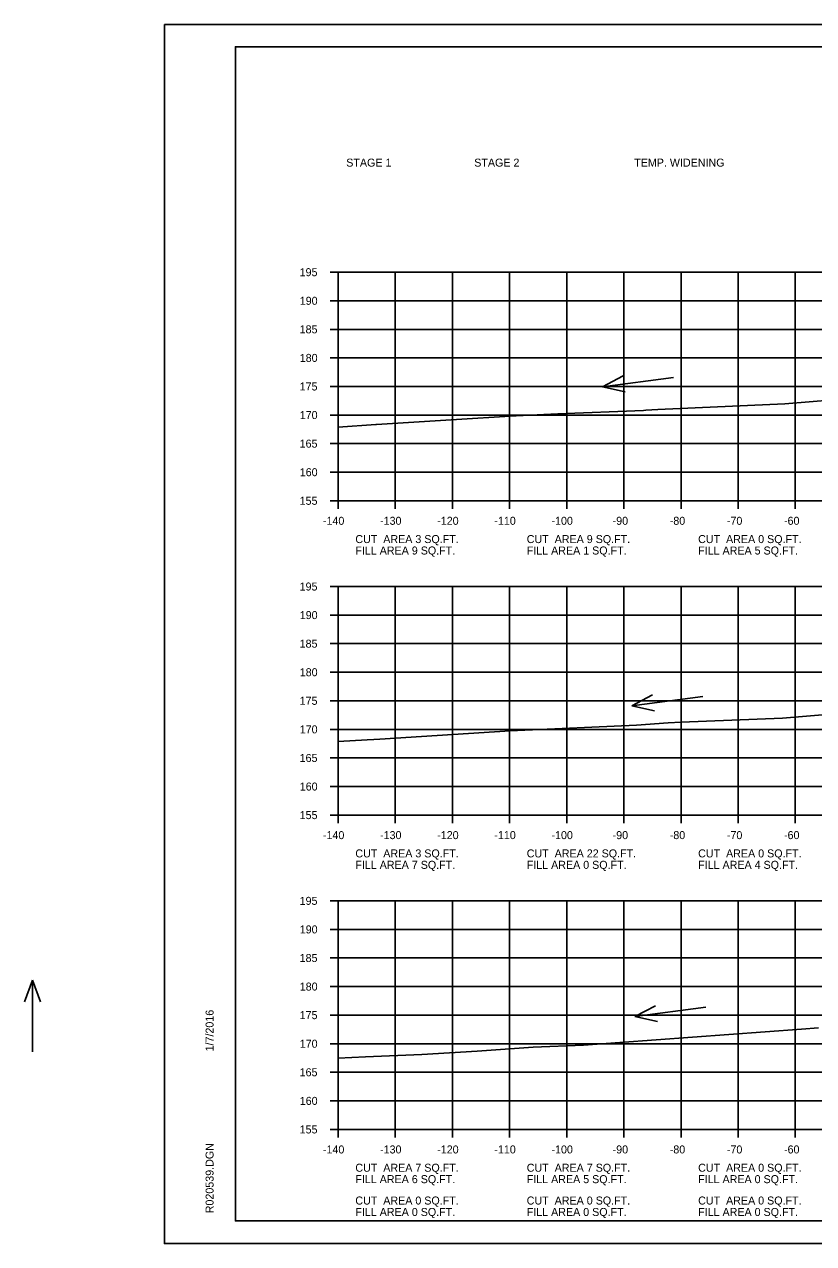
# Model space of a CAD drawing. Extents: x 915787 to 919910, y 133456 to 136717.
# Drawn here: x 916219.1 to 916357.2, y 133456 to 133669.4 of the extents above; entities that cross this region are included whole.
import ezdxf

# ---------------------------------------------------------------- set-up
doc = ezdxf.new("R2010")
doc.units = 0
for name, color, linetype in [('R_Axis', 7, 'Continuous'), ('R_Axis Annot', 7, 'Continuous'), ('R_Border', 7, 'Continuous'), ('R_Border Notes', 7, 'Continuous'), ('R_Exist Surface', 7, 'Continuous'), ('R_Grid', 7, 'Continuous'), ('R_No Plot', 7, 'Continuous'), ('R_Water Annot', 7, 'Continuous')]:
    doc.layers.add(name, color=color, linetype=linetype)

msp = doc.modelspace()

# ---------------------------------------------------------------- linework, layer by layer
at = {"layer": 'R_Axis'}
for p, q in [((916272.58, 133626.01), (916273.98, 133626.01)), ((916273.98, 133586.01), (916273.98, 133626.01)), ((916272.58, 133621.01), (916273.98, 133621.01)), ((916272.58, 133616.01), (916273.98, 133616.01)), ((916272.58, 133611.01), (916273.98, 133611.01)), ((916272.58, 133606.01), (916273.98, 133606.01)), ((916272.58, 133601.01), (916273.98, 133601.01)), ((916272.58, 133596.01), (916273.98, 133596.01)), ((916272.58, 133591.01), (916273.98, 133591.01)), ((916272.58, 133586.01), (916273.98, 133586.01)), ((916273.98, 133586.01), (916553.98, 133586.01)), ((916273.98, 133584.61), (916273.98, 133586.01)), ((916283.98, 133584.61), (916283.98, 133586.01)), ((916293.98, 133584.61), (916293.98, 133586.01)), ((916303.98, 133584.61), (916303.98, 133586.01)), ((916313.98, 133584.61), (916313.98, 133586.01)), ((916323.98, 133584.61), (916323.98, 133586.01)), ((916333.98, 133584.61), (916333.98, 133586.01)), ((916343.98, 133584.61), (916343.98, 133586.01)), ((916353.98, 133584.61), (916353.98, 133586.01)), ((916272.58, 133571.01), (916273.98, 133571.01)), ((916273.98, 133531.01), (916273.98, 133571.01)), ((916272.58, 133566.01), (916273.98, 133566.01)), ((916272.58, 133561.01), (916273.98, 133561.01)), ((916272.58, 133556.01), (916273.98, 133556.01)), ((916272.58, 133551.01), (916273.98, 133551.01)), ((916272.58, 133546.01), (916273.98, 133546.01)), ((916272.58, 133541.01), (916273.98, 133541.01)), ((916272.58, 133536.01), (916273.98, 133536.01)), ((916272.58, 133531.01), (916273.98, 133531.01)), ((916273.98, 133531.01), (916553.98, 133531.01)), ((916273.98, 133529.61), (916273.98, 133531.01)), ((916283.98, 133529.61), (916283.98, 133531.01)), ((916293.98, 133529.61), (916293.98, 133531.01)), ((916303.98, 133529.61), (916303.98, 133531.01)), ((916313.98, 133529.61), (916313.98, 133531.01)), ((916323.98, 133529.61), (916323.98, 133531.01)), ((916333.98, 133529.61), (916333.98, 133531.01)), ((916343.98, 133529.61), (916343.98, 133531.01)), ((916353.98, 133529.61), (916353.98, 133531.01)), ((916272.58, 133516.01), (916273.98, 133516.01)), ((916273.98, 133476.01), (916273.98, 133516.01)), ((916272.58, 133511.01), (916273.98, 133511.01)), ((916272.58, 133506.01), (916273.98, 133506.01)), ((916272.58, 133501.01), (916273.98, 133501.01)), ((916272.58, 133496.01), (916273.98, 133496.01)), ((916272.58, 133491.01), (916273.98, 133491.01)), ((916272.58, 133486.01), (916273.98, 133486.01)), ((916272.58, 133481.01), (916273.98, 133481.01)), ((916272.58, 133476.01), (916273.98, 133476.01)), ((916273.98, 133476.01), (916553.98, 133476.01)), ((916273.98, 133474.61), (916273.98, 133476.01)), ((916283.98, 133474.61), (916283.98, 133476.01)), ((916293.98, 133474.61), (916293.98, 133476.01)), ((916303.98, 133474.61), (916303.98, 133476.01)), ((916313.98, 133474.61), (916313.98, 133476.01)), ((916323.98, 133474.61), (916323.98, 133476.01)), ((916333.98, 133474.61), (916333.98, 133476.01)), ((916343.98, 133474.61), (916343.98, 133476.01)), ((916353.98, 133474.61), (916353.98, 133476.01))]:
    msp.add_line(p, q, dxfattribs=at)
at = {"layer": 'R_Border'}
for p, q in [((916255.98, 133665.47), (916572.16, 133665.47)), ((916255.98, 133460.01), (916255.98, 133665.47)), ((916255.98, 133460.01), (916255.98, 133460.01)), ((916572.16, 133460.01), (916255.98, 133460.01))]:
    msp.add_line(p, q, dxfattribs=at)
at = {"layer": 'R_Exist Surface'}
for points in [[(916273.98, 133598.91), (916280.55, 133599.33), (916280.71, 133599.34), (916293.73, 133600.17), (916305.04, 133600.88), (916305.14, 133600.89), (916312.44, 133601.2), (916327.43, 133601.83), (916327.8, 133601.84), (916329.93, 133601.97), (916352.13, 133602.95), (916364.93, 133604)], [(916273.98, 133543.89), (916279.05, 133544.21), (916280.2, 133544.26), (916281.28, 133544.3), (916304.08, 133545.74), (916305.35, 133545.83), (916326.18, 133546.72), (916331.72, 133547.13), (916334.02, 133547.28), (916351.75, 133547.99), (916354.57, 133548.22), (916365.66, 133549.14)], [(916273.98, 133488.49), (916278.75, 133488.69), (916288.59, 133489.1), (916298.32, 133489.7), (916308.11, 133490.4), (916316.93, 133490.77), (916355.08, 133493.56), (916358.02, 133493.77)]]:
    msp.add_lwpolyline(points, dxfattribs=at)
at = {"layer": 'R_Grid'}
for p, q in [((916273.98, 133626.01), (916553.98, 133626.01)), ((916273.98, 133586.01), (916273.98, 133626.01)), ((916283.98, 133586.01), (916283.98, 133626.01)), ((916293.98, 133586.01), (916293.98, 133626.01)), ((916303.98, 133586.01), (916303.98, 133626.01)), ((916313.98, 133586.01), (916313.98, 133626.01)), ((916323.98, 133586.01), (916323.98, 133626.01)), ((916333.98, 133586.01), (916333.98, 133626.01)), ((916343.98, 133586.01), (916343.98, 133626.01)), ((916353.98, 133586.01), (916353.98, 133626.01)), ((916273.98, 133621.01), (916553.98, 133621.01)), ((916273.98, 133616.01), (916553.98, 133616.01)), ((916273.98, 133611.01), (916553.98, 133611.01)), ((916273.98, 133606.01), (916553.98, 133606.01)), ((916273.98, 133601.01), (916553.98, 133601.01)), ((916273.98, 133596.01), (916553.98, 133596.01)), ((916273.98, 133591.01), (916553.98, 133591.01)), ((916273.98, 133586.01), (916553.98, 133586.01)), ((916273.98, 133571.01), (916553.98, 133571.01)), ((916273.98, 133531.01), (916273.98, 133571.01)), ((916283.98, 133531.01), (916283.98, 133571.01)), ((916293.98, 133531.01), (916293.98, 133571.01)), ((916303.98, 133531.01), (916303.98, 133571.01)), ((916313.98, 133531.01), (916313.98, 133571.01)), ((916323.98, 133531.01), (916323.98, 133571.01)), ((916333.98, 133531.01), (916333.98, 133571.01)), ((916343.98, 133531.01), (916343.98, 133571.01)), ((916353.98, 133531.01), (916353.98, 133571.01)), ((916273.98, 133566.01), (916553.98, 133566.01)), ((916273.98, 133561.01), (916553.98, 133561.01)), ((916273.98, 133556.01), (916553.98, 133556.01)), ((916273.98, 133551.01), (916553.98, 133551.01)), ((916273.98, 133546.01), (916553.98, 133546.01)), ((916273.98, 133541.01), (916553.98, 133541.01)), ((916273.98, 133536.01), (916553.98, 133536.01)), ((916273.98, 133531.01), (916553.98, 133531.01)), ((916273.98, 133516.01), (916553.98, 133516.01)), ((916273.98, 133476.01), (916273.98, 133516.01)), ((916283.98, 133476.01), (916283.98, 133516.01)), ((916293.98, 133476.01), (916293.98, 133516.01)), ((916303.98, 133476.01), (916303.98, 133516.01)), ((916313.98, 133476.01), (916313.98, 133516.01)), ((916323.98, 133476.01), (916323.98, 133516.01)), ((916333.98, 133476.01), (916333.98, 133516.01)), ((916343.98, 133476.01), (916343.98, 133516.01)), ((916353.98, 133476.01), (916353.98, 133516.01)), ((916273.98, 133511.01), (916553.98, 133511.01)), ((916273.98, 133506.01), (916553.98, 133506.01)), ((916273.98, 133501.01), (916553.98, 133501.01)), ((916273.98, 133496.01), (916553.98, 133496.01)), ((916273.98, 133491.01), (916553.98, 133491.01)), ((916273.98, 133486.01), (916553.98, 133486.01)), ((916273.98, 133481.01), (916553.98, 133481.01)), ((916273.98, 133476.01), (916553.98, 133476.01))]:
    msp.add_line(p, q, dxfattribs=at)
at = {"layer": 'R_No Plot'}
for p, q in [((916243.57, 133669.37), (916576.91, 133669.37)), ((916243.57, 133456.04), (916576.91, 133456.04))]:
    msp.add_line(p, q, dxfattribs=at)
for points in [[(916243.57, 133669.37), (916576.91, 133669.37), (916576.91, 133456.03), (916243.57, 133456.03)], [(916489.9, 133665.47), (916489.9, 133655.59), (916525.63, 133655.59), (916525.63, 133652.67), (916548.83, 133652.67), (916548.83, 133629.46), (916572.16, 133629.46), (916572.16, 133460.01), (916255.98, 133460.01), (916255.98, 133665.47)]]:
    msp.add_lwpolyline(points, close=True, dxfattribs=at)
at = {"layer": 'R_Water Annot'}
for p, q in [((916320.21, 133605.96), (916323.84, 133607.85)), ((916332.67, 133607.59), (916320.21, 133605.96)), ((916320.21, 133605.96), (916324.2, 133605.07)), ((916325.35, 133550.16), (916328.98, 133552.05)), ((916337.81, 133551.79), (916325.35, 133550.16)), ((916325.35, 133550.16), (916329.34, 133549.27)), ((916220.45, 133502.15), (916219.05, 133498.31)), ((916220.45, 133489.59), (916220.45, 133502.15)), ((916220.45, 133502.15), (916221.85, 133498.31)), ((916325.88, 133495.78), (916329.51, 133497.66)), ((916338.34, 133497.41), (916325.88, 133495.78)), ((916325.88, 133495.78), (916329.88, 133494.89))]:
    msp.add_line(p, q, dxfattribs=at)

# ---------------------------------------------------------------- texts
at = {"layer": 'R_Axis Annot'}
for s, p in [('195', (916267.23, 133625.31)), ('190', (916267.25, 133620.31)), ('185', (916267.23, 133615.31)), ('180', (916267.25, 133610.31)), ('175', (916267.23, 133605.31)), ('170', (916267.25, 133600.31)), ('165', (916267.23, 133595.31)), ('160', (916267.25, 133590.31)), ('155', (916267.23, 133585.31)), ('-140', (916271.31, 133581.81)), ('-130', (916281.31, 133581.81)), ('-120', (916291.31, 133581.81)), ('-110', (916301.31, 133581.81)), ('-100', (916311.31, 133581.81)), ('-90', (916322.01, 133581.81)), ('-80', (916332.01, 133581.81)), ('-70', (916342.01, 133581.81)), ('-60', (916352.01, 133581.81)), ('195', (916267.23, 133570.31)), ('190', (916267.25, 133565.31)), ('185', (916267.23, 133560.31)), ('180', (916267.25, 133555.31)), ('175', (916267.23, 133550.31)), ('170', (916267.25, 133545.31)), ('165', (916267.23, 133540.31)), ('160', (916267.25, 133535.31)), ('155', (916267.23, 133530.31)), ('-140', (916271.31, 133526.81)), ('-130', (916281.31, 133526.81)), ('-120', (916291.31, 133526.81)), ('-110', (916301.31, 133526.81)), ('-100', (916311.31, 133526.81)), ('-90', (916322.01, 133526.81)), ('-80', (916332.01, 133526.81)), ('-70', (916342.01, 133526.81)), ('-60', (916352.01, 133526.81)), ('195', (916267.23, 133515.31)), ('190', (916267.25, 133510.31)), ('185', (916267.23, 133505.31)), ('180', (916267.25, 133500.31)), ('175', (916267.23, 133495.31)), ('170', (916267.25, 133490.31)), ('165', (916267.23, 133485.31)), ('160', (916267.25, 133480.31)), ('155', (916267.23, 133475.31)), ('-140', (916271.31, 133471.81)), ('-130', (916281.31, 133471.81)), ('-120', (916291.31, 133471.81)), ('-110', (916301.31, 133471.81)), ('-100', (916311.31, 133471.81)), ('-90', (916322.01, 133471.81)), ('-80', (916332.01, 133471.81)), ('-70', (916342.01, 133471.81)), ('-60', (916352.01, 133471.81))]:
    msp.add_text(s, height=1.4, dxfattribs=at).set_placement(p)
at = {"layer": 'R_Border'}
for s, p in [('1/7/2016', (916252.17, 133489.66)), ('R020539.DGN', (916252.17, 133461.34))]:
    msp.add_text(s, height=1.4, rotation=90, dxfattribs=at).set_placement(p)
at = {"layer": 'R_Border Notes'}
for s, p in [('STAGE 1', (916275.39, 133644.48)), ('STAGE 2', (916297.79, 133644.48)), ('TEMP. WIDENING', (916325.79, 133644.48)), ('CUT  AREA 3 SQ.FT.', (916276.98, 133578.61)), ('CUT  AREA 9 SQ.FT.', (916306.98, 133578.61)), ('CUT  AREA 0 SQ.FT.', (916336.98, 133578.61)), ('FILL AREA 9 SQ.FT.', (916276.98, 133576.61)), ('FILL AREA 1 SQ.FT.', (916306.98, 133576.61)), ('FILL AREA 5 SQ.FT.', (916336.98, 133576.61)), ('CUT  AREA 3 SQ.FT.', (916276.98, 133523.61)), ('CUT  AREA 22 SQ.FT.', (916306.98, 133523.61)), ('CUT  AREA 0 SQ.FT.', (916336.98, 133523.61)), ('FILL AREA 7 SQ.FT.', (916276.98, 133521.61)), ('FILL AREA 0 SQ.FT.', (916306.98, 133521.61)), ('FILL AREA 4 SQ.FT.', (916336.98, 133521.61)), ('CUT  AREA 7 SQ.FT.', (916276.98, 133468.61)), ('CUT  AREA 7 SQ.FT.', (916306.98, 133468.61)), ('CUT  AREA 0 SQ.FT.', (916336.98, 133468.61)), ('FILL AREA 6 SQ.FT.', (916276.98, 133466.61)), ('FILL AREA 5 SQ.FT.', (916306.98, 133466.61)), ('FILL AREA 0 SQ.FT.', (916336.98, 133466.61)), ('CUT  AREA 0 SQ.FT.', (916276.98, 133462.87)), ('CUT  AREA 0 SQ.FT.', (916306.98, 133462.87)), ('CUT  AREA 0 SQ.FT.', (916336.98, 133462.87)), ('FILL AREA 0 SQ.FT.', (916276.98, 133460.87)), ('FILL AREA 0 SQ.FT.', (916306.98, 133460.87)), ('FILL AREA 0 SQ.FT.', (916336.98, 133460.87))]:
    msp.add_text(s, height=1.4, dxfattribs=at).set_placement(p)

doc.saveas('drawing.dxf')
